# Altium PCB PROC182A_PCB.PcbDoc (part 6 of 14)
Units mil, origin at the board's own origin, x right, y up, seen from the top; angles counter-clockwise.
Board outline 3168.31 x 3700.79 mil, 8 copper layers (Top Layer, L2_GND1, L3_SIG1, L4_PWR1, L5_PWR2, L6_SIG2, L7_GND2, Bottom Layer), stack 58.1 mil thick; 580 components, 391 nets, 8314 pads, 4370 vias.
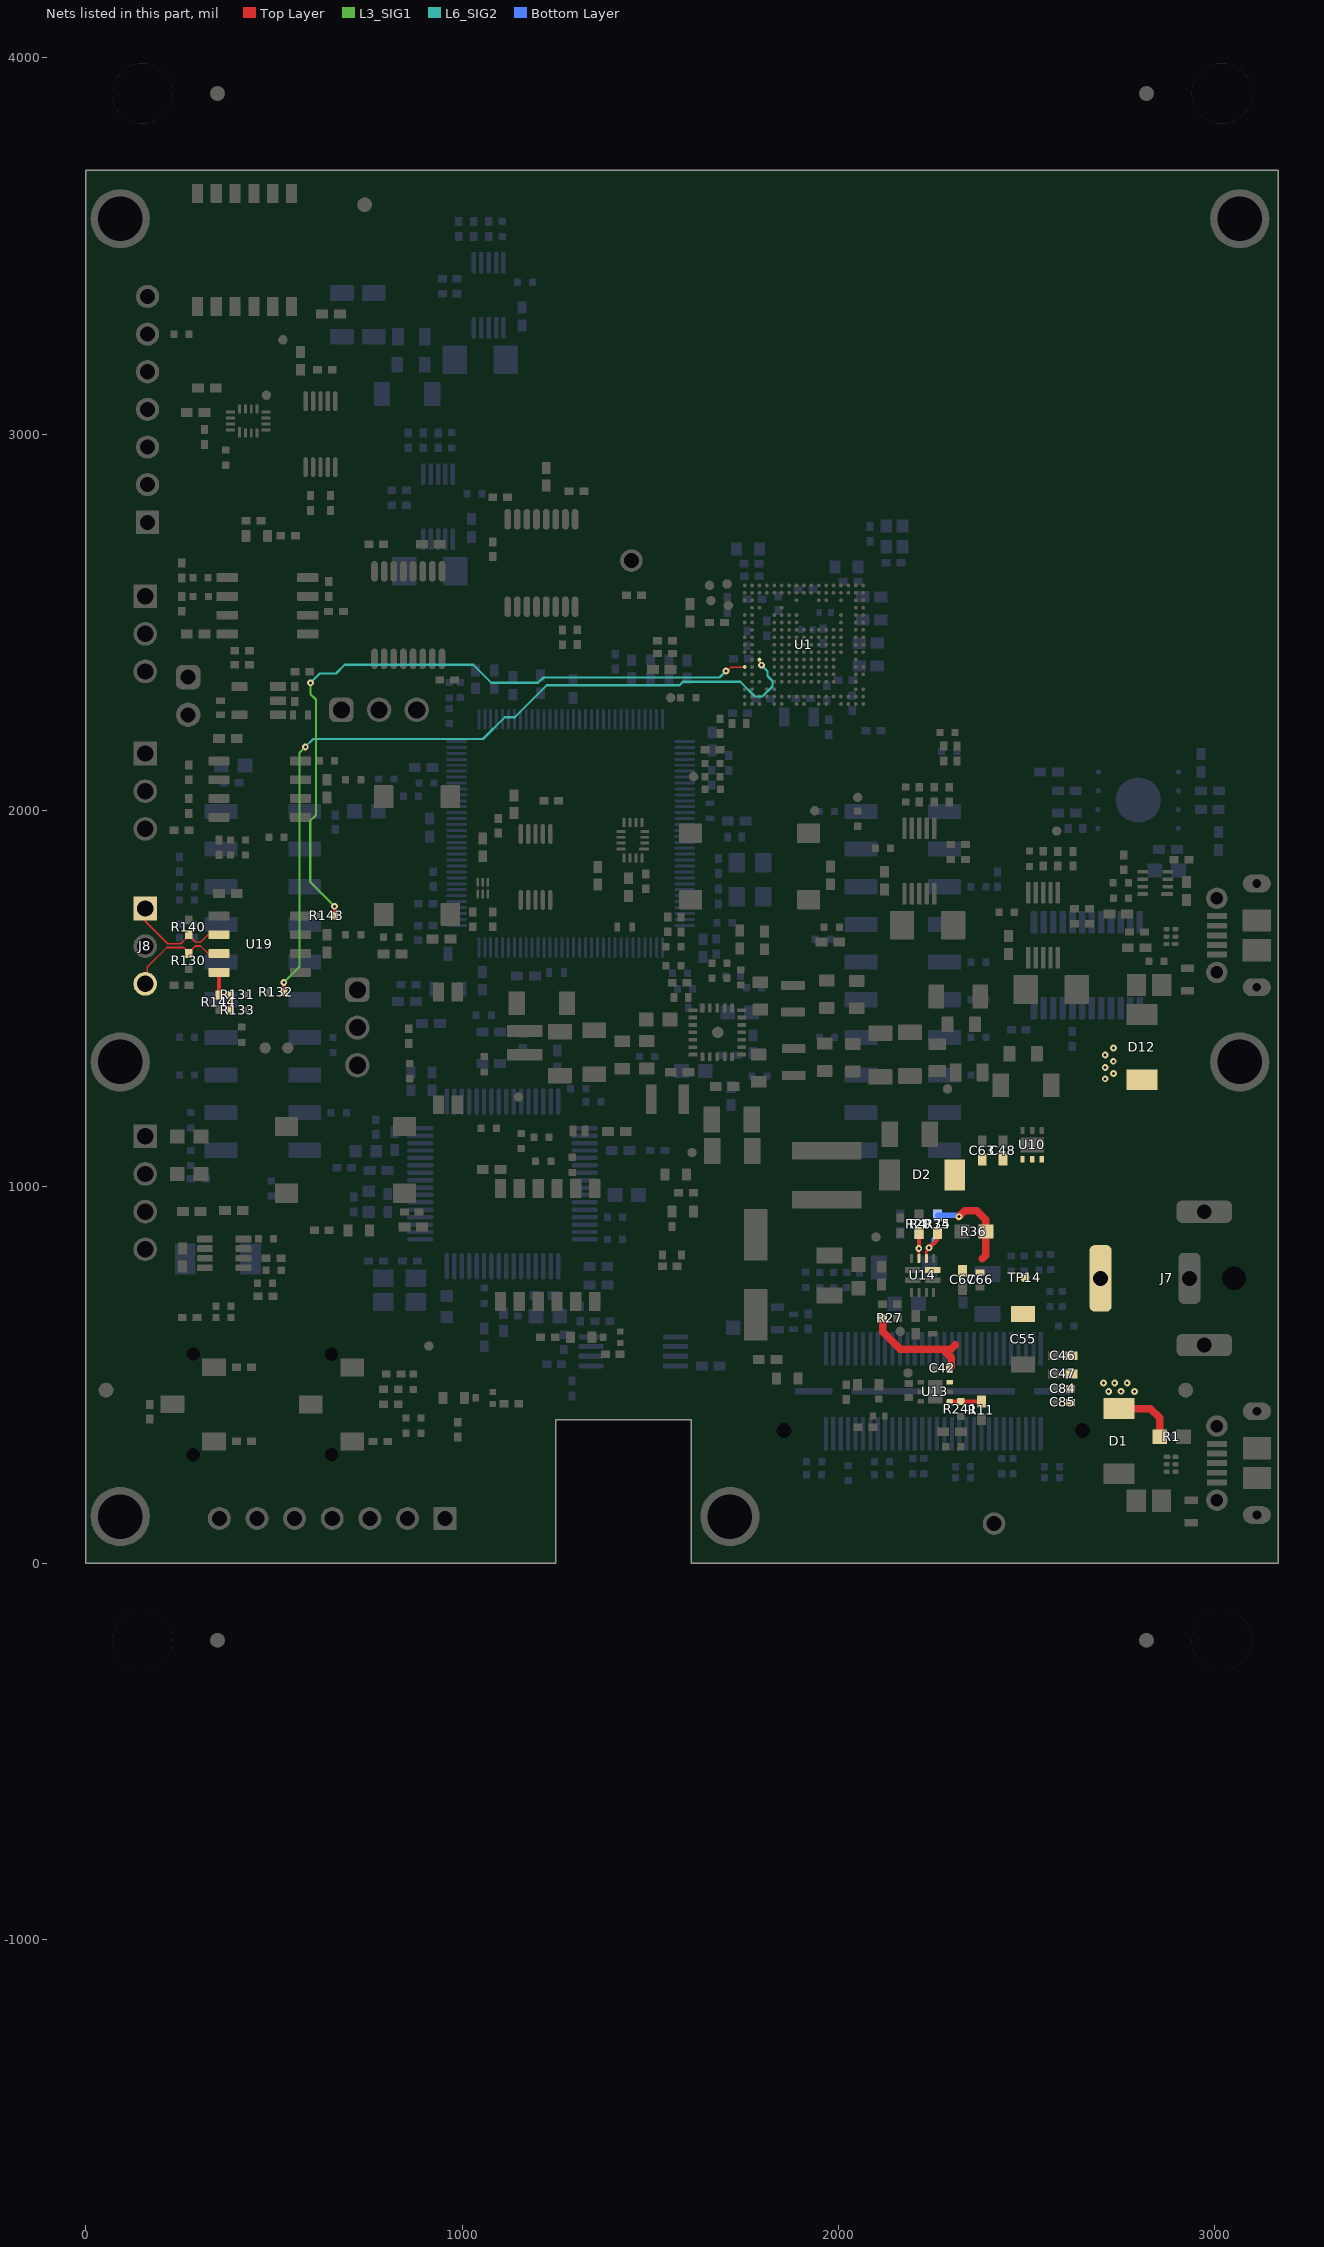
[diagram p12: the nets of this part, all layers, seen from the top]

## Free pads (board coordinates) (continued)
  round 5 on Mech16: 1(836.95,1440.45) 1(836.95,1440.45) 1(836.95,1491.45) 1(836.95,1491.45) 1(848.2,1416.45) 1(848.2,1416.45) 1(848.2,1424.6) 1(848.2,1424.6) 1(848.2,1426.88) 1(848.2,1426.88) 1(848.2,1434.38) 1(848.2,1434.38) 1(848.2,1440.45) 1(848.2,1440.45) 1(857.23,1143.96) 1(857.23,1143.96) 1(857.23,1143.98) 1(857.23,1143.98) 1(857.23,1200.98) 1(857.23,1200.98) 1(857.23,1201) 1(857.23,1201) 1(860.23,1140.98) 1(860.23,1140.98) 1(860.23,1203.98) 1(860.23,1203.98) 1(865.7,1416.45) 1(865.7,1416.45) 1(865.7,1424.6) 1(865.7,1424.6) 1(865.7,1426.88) 1(865.7,1426.88) 1(865.7,1434.38) 1(865.7,1434.38) 1(865.7,1440.45) 1(865.7,1440.45) 1(869.85,1116.48) 1(869.85,1116.48) 1(869.85,1125.03) 1(869.85,1125.03) 1(869.85,1128.67) 1(869.85,1128.67) 1(869.85,1129.93) 1(869.85,1129.93) 1(869.85,1139.9) 1(869.85,1139.9) 1(869.85,1140.98) 1(869.85,1140.98) 1(869.85,1203.98) 1(869.85,1203.98) 1(869.85,1205.07) 1(869.85,1205.07) 1(869.85,1215.03) 1(869.85,1215.03) 1(869.85,1216.29) 1(869.85,1216.29) 1(869.85,1219.93) 1(869.85,1219.93) 1(869.85,1228.48) 1(869.85,1228.48) 1(884.61,1116.48) 1(884.61,1116.48) 1(884.61,1125.03) 1(884.61,1125.03) 1(884.61,1128.67) 1(884.61,1128.67) 1(884.61,1129.93) 1(884.61,1129.93) 1(884.61,1139.9) 1(884.61,1139.9) 1(884.61,1140.98) 1(884.61,1140.98) 1(884.61,1203.98) 1(884.61,1203.98) 1(884.61,1205.07) 1(884.61,1205.07) 1(884.61,1215.03) 1(884.61,1215.03) 1(884.61,1216.29) 1(884.61,1216.29) 1(884.61,1219.93) 1(884.61,1219.93) 1(884.61,1228.48) 1(884.61,1228.48) 1(885.7,1491.45) 1(885.7,1491.45) 1(885.7,1497.51) 1(885.7,1497.51) 1(885.7,1505.01) 1(885.7,1505.01) 1(885.7,1507.3) 1(885.7,1507.3) 1(885.7,1515.45) 1(885.7,1515.45) 1(903.2,1491.45) 1(903.2,1491.45) 1(903.2,1497.51) 1(903.2,1497.51) 1(903.2,1505.01) 1(903.2,1505.01) 1(903.2,1507.3) 1(903.2,1507.3) 1(903.2,1515.45) 1(903.2,1515.45) 1(907.35,1116.48) 1(907.35,1116.48) 1(907.35,1125.03) 1(907.35,1125.03) 1(907.35,1128.67) 1(907.35,1128.67) 1(907.35,1129.93) 1(907.35,1129.93) 1(907.35,1139.9) 1(907.35,1139.9) 1(907.35,1140.98) 1(907.35,1140.98) 1(907.35,1203.98) 1(907.35,1203.98) 1(907.35,1205.07) 1(907.35,1205.07) 1(907.35,1215.03) 1(907.35,1215.03) 1(907.35,1216.29) 1(907.35,1216.29) 1(907.35,1219.93) 1(907.35,1219.93) 1(907.35,1228.48) 1(907.35,1228.48) 1(922.11,1116.48) 1(922.11,1116.48) 1(922.11,1125.03) 1(922.11,1125.03) 1(922.11,1128.67) 1(922.11,1128.67) 1(922.11,1129.93) 1(922.11,1129.93) 1(922.11,1139.9) 1(922.11,1139.9) 1(922.11,1140.98) 1(922.11,1140.98) 1(922.11,1203.98) 1(922.11,1203.98) 1(922.11,1205.07) 1(922.11,1205.07) 1(922.11,1215.03) 1(922.11,1215.03) 1(922.11,1216.29) 1(922.11,1216.29) 1(922.11,1219.93) 1(922.11,1219.93) 1(922.11,1228.48) 1(922.11,1228.48) 1(923.2,1416.45) 1(923.2,1416.45) 1(923.2,1424.6) 1(923.2,1424.6) 1(923.2,1426.88) 1(923.2,1426.88) 1(923.2,1434.38) 1(923.2,1434.38) 1(923.2,1440.45) 1(923.2,1440.45) 1(940.7,1416.45) 1(940.7,1416.45) 1(940.7,1424.6) 1(940.7,1424.6) 1(940.7,1426.88) 1(940.7,1426.88) 1(940.7,1434.38) 1(940.7,1434.38) 1(940.7,1440.45) 1(940.7,1440.45) 1(944.85,1116.48) 1(944.85,1116.48) 1(944.85,1125.03) 1(944.85,1125.03) 1(944.85,1128.67) 1(944.85,1128.67) 1(944.85,1129.93) 1(944.85,1129.93) 1(944.85,1139.9) 1(944.85,1139.9) 1(944.85,1140.98) 1(944.85,1140.98) 1(944.85,1203.98) 1(944.85,1203.98) 1(944.85,1205.07) 1(944.85,1205.07) 1(944.85,1215.03) 1(944.85,1215.03) 1(944.85,1216.29) 1(944.85,1216.29) 1(944.85,1219.93) 1(944.85,1219.93) 1(944.85,1228.48) 1(944.85,1228.48) 1(950.98,1149.81) 1(950.98,1149.81) 1(950.98,1159.8) 1(950.98,1159.8) 1(951.95,1440.45) 1(951.95,1440.45) 1(951.95,1491.45) 1(951.95,1491.45) 1(959.61,1116.48) 1(959.61,1116.48) 1(959.61,1125.03) 1(959.61,1125.03) 1(959.61,1128.67) 1(959.61,1128.67) 1(959.61,1129.93) 1(959.61,1129.93) 1(959.61,1139.9) 1(959.61,1139.9) 1(959.61,1140.98) 1(959.61,1140.98) 1(959.61,1203.98) 1(959.61,1203.98) 1(959.61,1205.07) 1(959.61,1205.07) 1(959.61,1215.03) 1(959.61,1215.03) 1(959.61,1216.29) 1(959.61,1216.29) 1(959.61,1219.93) 1(959.61,1219.93) 1(959.61,1228.48) 1(959.61,1228.48) 1(969.24,1140.98) 1(969.24,1140.98) 1(969.24,1203.98) 1(969.24,1203.98) 1(972.23,1143.96) 1(972.23,1143.96) 1(972.23,1143.98) 1(972.23,1143.98) 1(972.23,1200.98) 1(972.23,1200.98) 1(972.23,1201) 1(972.23,1201) 1(1078.31,-1645.55) 1(1078.31,-1645.55) 1(1078.31,-1145.55) 1(1078.31,-1145.55) 1(1668.61,1080.75) 1(1668.61,1080.75) 1(1668.61,1090.6) 1(1668.61,1090.6) 1(1668.61,1106.35) 1(1668.61,1106.35) 1(1668.61,1116.19) 1(1668.61,1116.19) 1(1668.61,1131.94) 1(1668.61,1131.94) 1(1668.61,1141.78) 1(1668.61,1141.78) 1(1668.61,1157.53) 1(1668.61,1157.53) 1(1668.61,1167.37) 1(1668.61,1167.37) 1(1680.42,1080.75) 1(1680.42,1080.75) 1(1680.42,1090.6) 1(1680.42,1090.6) 1(1680.42,1106.35) 1(1680.42,1106.35) 1(1680.42,1116.19) 1(1680.42,1116.19) 1(1680.42,1131.94) 1(1680.42,1131.94) 1(1680.42,1141.78) 1(1680.42,1141.78) 1(1680.42,1157.53) 1(1680.42,1157.53) 1(1680.42,1167.37) 1(1680.42,1167.37) 1(1685.84,1080.75) 1(1685.84,1080.75) 1(1685.84,1090.6) 1(1685.84,1090.6) 1(1685.84,1106.35) 1(1685.84,1106.35) 1(1685.84,1116.19) 1(1685.84,1116.19) 1(1685.84,1131.94) 1(1685.84,1131.94) 1(1685.84,1141.78) 1(1685.84,1141.78) 1(1685.84,1157.53) 1(1685.84,1157.53) 1(1685.84,1167.37) 1(1685.84,1167.37) 1(1691.06,1080.75) 1(1691.06,1080.75) 1(1691.06,1090.6) 1(1691.06,1090.6) 1(1691.06,1106.35) 1(1691.06,1106.35) 1(1691.06,1116.19) 1(1691.06,1116.19) 1(1691.06,1131.94) 1(1691.06,1131.94) 1(1691.06,1141.78) 1(1691.06,1141.78) 1(1691.06,1157.53) 1(1691.06,1157.53) 1(1691.06,1167.37) 1(1691.06,1167.37) 1(1700.1,1080.75) 1(1700.1,1080.75) 1(1700.1,1090.6) 1(1700.1,1090.6) 1(1700.1,1106.35) 1(1700.1,1106.35) 1(1700.1,1116.19) 1(1700.1,1116.19) 1(1700.1,1131.94) 1(1700.1,1131.94) 1(1700.1,1141.78) 1(1700.1,1141.78) 1(1700.1,1157.53) 1(1700.1,1157.53) 1(1700.1,1167.37) 1(1700.1,1167.37) 1(1706.01,1062.84) 1(1706.01,1062.84) 1(1706.01,1062.84) 1(1706.01,1080.75) 1(1706.01,1080.75) 1(1706.01,1090.6) 1(1706.01,1090.6) 1(1706.01,1106.35) 1(1706.01,1106.35) 1(1706.01,1116.19) 1(1706.01,1116.19) 1(1706.01,1131.94) 1(1706.01,1131.94) 1(1706.01,1141.78) 1(1706.01,1141.78) 1(1706.01,1157.53) 1(1706.01,1157.53) 1(1706.01,1167.37) 1(1706.01,1167.37) 1(1706.01,1184.89) 1(1706.01,1184.89) 1(1706.01,1184.89) 1(1709.77,1066.61) 1(1709.77,1066.61) 1(1709.77,1066.61) 1(1709.77,1181.12) 1(1709.77,1181.12) 1(1709.77,1181.12) 1(1724.56,931.83) 1(1724.56,931.83) 1(1724.56,942.51) 1(1724.56,942.51) 1(1724.56,951.51) 1(1724.56,951.51) 1(1724.56,962.19) 1(1724.56,962.19) 1(1724.56,990.87) 1(1724.56,990.87) 1(1724.56,1001.55) 1(1724.56,1001.55) 1(1724.56,922.83) 1(1724.56,922.83) 1(1724.56,971.19) 1(1724.56,971.19) 1(1724.56,981.87) 1(1724.56,981.87) 1(1724.56,1010.55) 1(1724.56,1010.55) 1(1725.69,1074.65) 1(1725.69,1074.65) 1(1725.69,1090.4) 1(1725.69,1090.4) 1(1734,922.83) 1(1734,922.83) 1(1734,931.83) 1(1734,931.83) 1(1734,942.51) 1(1734,942.51) 1(1734,951.51) 1(1734,951.51) 1(1734,962.19) 1(1734,962.19) 1(1734,971.19) 1(1734,971.19) 1(1734,981.87) 1(1734,981.87) 1(1734,990.87) 1(1734,990.87) 1(1734,1001.55) 1(1734,1001.55) 1(1734,1010.55) 1(1734,1010.55) 1(1738.72,922.83) 1(1738.72,922.83) 1(1738.72,931.83) 1(1738.72,931.83) 1(1738.72,942.51) 1(1738.72,942.51) 1(1738.72,951.51) 1(1738.72,951.51) 1(1738.72,962.19) 1(1738.72,962.19) 1(1738.72,971.19) 1(1738.72,971.19) 1(1738.72,981.87) 1(1738.72,981.87) 1(1738.72,990.87) 1(1738.72,990.87) 1(1738.72,1001.55) 1(1738.72,1001.55) 1(1738.72,1010.55) 1(1738.72,1010.55) 1(1738.85,922.83) 1(1738.85,922.83) 1(1738.85,931.83) 1(1738.85,931.83) 1(1738.85,942.51) 1(1738.85,942.51) 1(1738.85,951.51) 1(1738.85,951.51) 1(1738.85,962.19) 1(1738.85,962.19) 1(1738.85,971.19) 1(1738.85,971.19) 1(1738.85,981.87) 1(1738.85,981.87) 1(1738.85,990.87) 1(1738.85,990.87) 1(1738.85,1001.55) 1(1738.85,1001.55) 1(1738.85,1010.55) 1(1738.85,1010.55) 1(1750.8,922.83) 1(1750.8,922.83) 1(1750.8,931.83) 1(1750.8,931.83) 1(1750.8,942.51) 1(1750.8,942.51) 1(1750.8,951.51) 1(1750.8,951.51) 1(1750.8,962.19) 1(1750.8,962.19) 1(1750.8,971.19) 1(1750.8,971.19) 1(1750.8,981.87) 1(1750.8,981.87) 1(1750.8,990.87) 1(1750.8,990.87) 1(1750.8,1001.55) 1(1750.8,1001.55) 1(1750.8,1010.55) 1(1750.8,1010.55) 1(1762.06,912.69) 1(1762.06,912.69) 1(1762.06,922.83) 1(1762.06,922.83) 1(1762.06,931.83) 1(1762.06,931.83) 1(1762.06,942.51) 1(1762.06,942.51) 1(1762.06,951.51) 1(1762.06,951.51) 1(1762.06,962.19) 1(1762.06,962.19) 1(1762.06,971.19) 1(1762.06,971.19) 1(1762.06,981.87) 1(1762.06,981.87) 1(1762.06,990.87) 1(1762.06,990.87) 1(1762.06,1001.55) 1(1762.06,1001.55) 1(1762.06,1010.55) 1(1762.06,1010.55) 1(1762.06,1020.69) 1(1762.06,1020.69) 1(1762.07,912.59) 1(1762.07,912.59) 1(1762.07,1020.8) 1(1762.07,1020.8) 1(1763.15,145.77) 1(1763.15,145.77) 1(1763.15,225.77) 1(1763.15,225.77) 1(1763.15,541.91) 1(1763.15,541.91) 1(1763.15,621.91) 1(1763.15,621.91) 1(1766.96,907.7) 1(1766.96,907.7) 1(1766.96,1025.69) 1(1766.96,1025.69) 1(1767.06,907.69) 1(1767.06,907.69) 1(1767.06,1025.69) 1(1767.06,1025.69) 1(1769.06,928.69) 1(1769.06,928.69) 1(1782.87,-204.39) 1(1782.87,-204.39) 1(1782.87,-193.71) 1(1782.87,-193.71) 1(1782.87,-184.71) 1(1782.87,-184.71) 1(1782.87,-174.03) 1(1782.87,-174.03) 1(1782.87,-145.35) 1(1782.87,-145.35) 1(1782.87,-134.67) 1(1782.87,-134.67) 1(1782.87,-213.39) 1(1782.87,-213.39) 1(1782.87,-165.03) 1(1782.87,-165.03) 1(1782.87,-154.35) 1(1782.87,-154.35) 1(1782.87,-125.67) 1(1782.87,-125.67) 1(1792.31,-213.39) 1(1792.31,-213.39) 1(1792.31,-204.39) 1(1792.31,-204.39) 1(1792.31,-193.71) 1(1792.31,-193.71) 1(1792.31,-184.71) 1(1792.31,-184.71) 1(1792.31,-174.03) 1(1792.31,-174.03) 1(1792.31,-165.03) 1(1792.31,-165.03) 1(1792.31,-154.35) 1(1792.31,-154.35) 1(1792.31,-145.35) 1(1792.31,-145.35) 1(1792.31,-134.67) 1(1792.31,-134.67) 1(1792.31,-125.67) 1(1792.31,-125.67) 1(1797.02,-213.39) 1(1797.02,-213.39) 1(1797.02,-204.39) 1(1797.02,-204.39) 1(1797.02,-193.71) 1(1797.02,-193.71) 1(1797.02,-184.71) 1(1797.02,-184.71) 1(1797.02,-174.03) 1(1797.02,-174.03) 1(1797.02,-165.03) 1(1797.02,-165.03) 1(1797.02,-154.35) 1(1797.02,-154.35) 1(1797.02,-145.35) 1(1797.02,-145.35) 1(1797.02,-134.67) 1(1797.02,-134.67) 1(1797.02,-125.67) 1(1797.02,-125.67) 1(1797.06,928.69) 1(1797.06,928.69) 1(1797.15,-213.39) 1(1797.15,-213.39) 1(1797.15,-204.39) 1(1797.15,-204.39) 1(1797.15,-193.71) 1(1797.15,-193.71) 1(1797.15,-184.71) 1(1797.15,-184.71) 1(1797.15,-174.03) 1(1797.15,-174.03) 1(1797.15,-165.03) 1(1797.15,-165.03) 1(1797.15,-154.35) 1(1797.15,-154.35) 1(1797.15,-145.35) 1(1797.15,-145.35) 1(1797.15,-134.67) 1(1797.15,-134.67) 1(1797.15,-125.67) 1(1797.15,-125.67) 1(1809.11,-213.39) 1(1809.11,-213.39) 1(1809.11,-204.39) 1(1809.11,-204.39) 1(1809.11,-193.71) 1(1809.11,-193.71) 1(1809.11,-184.71) 1(1809.11,-184.71) 1(1809.11,-174.03) 1(1809.11,-174.03) 1(1809.11,-165.03) 1(1809.11,-165.03) 1(1809.11,-154.35) 1(1809.11,-154.35) 1(1809.11,-145.35) 1(1809.11,-145.35) 1(1809.11,-134.67) 1(1809.11,-134.67) 1(1809.11,-125.67) 1(1809.11,-125.67) 1(1820.37,-223.53) 1(1820.37,-223.53) 1(1820.37,-213.39) 1(1820.37,-213.39) 1(1820.37,-204.39) 1(1820.37,-204.39) 1(1820.37,-193.71) 1(1820.37,-193.71) 1(1820.37,-184.71) 1(1820.37,-184.71) 1(1820.37,-174.03) 1(1820.37,-174.03) 1(1820.37,-165.03) 1(1820.37,-165.03) 1(1820.37,-154.35) 1(1820.37,-154.35) 1(1820.37,-145.35) 1(1820.37,-145.35) 1(1820.37,-134.67) 1(1820.37,-134.67) 1(1820.37,-125.67) 1(1820.37,-125.67) 1(1820.37,-115.53) 1(1820.37,-115.53) 1(1820.37,-223.64) 1(1820.37,-223.64) 1(1820.37,-115.42) 1(1820.37,-115.42) 1(1825.26,-228.53) 1(1825.26,-228.53) 1(1825.26,-110.53) 1(1825.26,-110.53) 1(1825.37,-228.53) 1(1825.37,-228.53) 1(1825.37,-110.53) 1(1825.37,-110.53) 1(1827.37,-207.53) 1(1827.37,-207.53) 1(1855.37,-207.53) 1(1855.37,-207.53) 1(1875.06,907.69) 1(1875.06,907.69) 1(1875.06,1025.69) 1(1875.06,1025.69) 1(1875.17,907.7) 1(1875.17,907.7) 1(1875.17,1025.69) 1(1875.17,1025.69) 1(1879.41,1066.61) 1(1879.41,1066.61) 1(1879.41,1066.61) 1(1879.41,1181.12) 1(1879.41,1181.12) 1(1879.41,1181.12) 1(1880.06,912.59) 1(1880.06,912.59) 1(1880.06,1020.8) 1(1880.06,1020.8) 1(1880.06,912.69) 1(1880.06,912.69) 1(1880.06,922.83) 1(1880.06,922.83) 1(1880.06,931.83) 1(1880.06,931.83) 1(1880.06,942.51) 1(1880.06,942.51) 1(1880.06,951.51) 1(1880.06,951.51) 1(1880.06,962.19) 1(1880.06,962.19) 1(1880.06,971.19) 1(1880.06,971.19) 1(1880.06,981.87) 1(1880.06,981.87) 1(1880.06,990.87) 1(1880.06,990.87) 1(1880.06,1001.55) 1(1880.06,1001.55) 1(1880.06,1010.55) 1(1880.06,1010.55) 1(1880.06,1020.69) 1(1880.06,1020.69) 1(1883.17,1062.84) 1(1883.17,1062.84) 1(1883.17,1062.84) 1(1883.17,1080.75) 1(1883.17,1080.75) 1(1883.17,1090.6) 1(1883.17,1090.6) 1(1883.17,1106.35) 1(1883.17,1106.35) 1(1883.17,1116.19) 1(1883.17,1116.19) 1(1883.17,1131.94) 1(1883.17,1131.94) 1(1883.17,1141.78) 1(1883.17,1141.78) 1(1883.17,1157.53) 1(1883.17,1157.53) 1(1883.17,1167.37) 1(1883.17,1167.37) 1(1883.17,1184.89) 1(1883.17,1184.89) 1(1883.17,1184.89) 1(1889.08,1080.75) 1(1889.08,1080.75) 1(1889.08,1090.6) 1(1889.08,1090.6) 1(1889.08,1106.35) 1(1889.08,1106.35) 1(1889.08,1116.19) 1(1889.08,1116.19) 1(1889.08,1131.94) 1(1889.08,1131.94) 1(1889.08,1141.78) 1(1889.08,1141.78) 1(1889.08,1157.53) 1(1889.08,1157.53) 1(1889.08,1167.37) 1(1889.08,1167.37) 1(1891.33,922.83) 1(1891.33,922.83) 1(1891.33,931.83) 1(1891.33,931.83) 1(1891.33,942.51) 1(1891.33,942.51) 1(1891.33,951.51) 1(1891.33,951.51) 1(1891.33,962.19) 1(1891.33,962.19) 1(1891.33,971.19) 1(1891.33,971.19) 1(1891.33,981.87) 1(1891.33,981.87) 1(1891.33,1010.55) 1(1891.33,1010.55) 1(1891.33,990.87) 1(1891.33,990.87) 1(1891.33,1001.55) 1(1891.33,1001.55) 1(1898.12,1080.75) 1(1898.12,1080.75) 1(1898.12,1090.6) 1(1898.12,1090.6) 1(1898.12,1106.35) 1(1898.12,1106.35) 1(1898.12,1116.19) 1(1898.12,1116.19) 1(1898.12,1131.94) 1(1898.12,1131.94) 1(1898.12,1141.78) 1(1898.12,1141.78) 1(1898.12,1157.53) 1(1898.12,1157.53) 1(1898.12,1167.37) 1(1898.12,1167.37) 1(1903.28,922.83) 1(1903.28,922.83) 1(1903.28,931.83) 1(1903.28,931.83) 1(1903.28,942.51) 1(1903.28,942.51) 1(1903.28,951.51) 1(1903.28,951.51) 1(1903.28,962.19) 1(1903.28,962.19) 1(1903.28,971.19) 1(1903.28,971.19) 1(1903.28,981.87) 1(1903.28,981.87) 1(1903.28,990.87) 1(1903.28,990.87) 1(1903.28,1001.55) 1(1903.28,1001.55) 1(1903.28,1010.55) 1(1903.28,1010.55) 1(1903.34,1080.75) 1(1903.34,1080.75) 1(1903.34,1090.6) 1(1903.34,1090.6) 1(1903.34,1106.35) 1(1903.34,1106.35) 1(1903.34,1116.19) 1(1903.34,1116.19) 1(1903.34,1131.94) 1(1903.34,1131.94) 1(1903.34,1141.78) 1(1903.34,1141.78) 1(1903.34,1157.53) 1(1903.34,1157.53) 1(1903.34,1167.37) 1(1903.34,1167.37) 1(1903.41,990.87) 1(1903.41,990.87) 1(1903.41,1001.55) 1(1903.41,1001.55) 1(1903.41,922.83) 1(1903.41,922.83) 1(1903.41,931.83) 1(1903.41,931.83) 1(1903.41,942.51) 1(1903.41,942.51) 1(1903.41,951.51) 1(1903.41,951.51) 1(1903.41,962.19) 1(1903.41,962.19) 1(1903.41,971.19) 1(1903.41,971.19) 1(1903.41,981.87) 1(1903.41,981.87) 1(1903.41,1010.55) 1(1903.41,1010.55) 1(1908.13,922.83) 1(1908.13,922.83) 1(1908.13,931.83) 1(1908.13,931.83) 1(1908.13,942.51) 1(1908.13,942.51) 1(1908.13,951.51) 1(1908.13,951.51) 1(1908.13,962.19) 1(1908.13,962.19) 1(1908.13,971.19) 1(1908.13,971.19) 1(1908.13,981.87) 1(1908.13,981.87) 1(1908.13,990.87) 1(1908.13,990.87) 1(1908.13,1001.55) 1(1908.13,1001.55) 1(1908.13,1010.55) 1(1908.13,1010.55) 1(1908.76,1080.75) 1(1908.76,1080.75) 1(1908.76,1090.6) 1(1908.76,1090.6) 1(1908.76,1106.35) 1(1908.76,1106.35) 1(1908.76,1116.19) 1(1908.76,1116.19) 1(1908.76,1131.94) 1(1908.76,1131.94) 1(1908.76,1141.78) 1(1908.76,1141.78) 1(1908.76,1157.53) 1(1908.76,1157.53) 1(1908.76,1167.37) 1(1908.76,1167.37) 1(1909.15,541.91) 1(1909.15,541.91) 1(1909.15,621.91) 1(1909.15,621.91) 1(1911.15,145.77) 1(1911.15,145.77) 1(1911.15,145.91) 1(1911.15,145.91) 1(1911.15,225.77) 1(1911.15,225.77) 1(1911.15,225.91) 1(1911.15,225.91) 1(1911.15,541.91) 1(1911.15,541.91) 1(1911.15,621.91) 1(1911.15,621.91) 1(1917.56,922.83) 1(1917.56,922.83) 1(1917.56,931.83) 1(1917.56,931.83) 1(1917.56,942.51) 1(1917.56,942.51) 1(1917.56,951.51) 1(1917.56,951.51) 1(1917.56,962.19) 1(1917.56,962.19) 1(1917.56,971.19) 1(1917.56,971.19) 1(1917.56,981.87) 1(1917.56,981.87) 1(1917.56,990.87) 1(1917.56,990.87) 1(1917.56,1001.55) 1(1917.56,1001.55) 1(1917.56,1010.55) 1(1917.56,1010.55) 1(1920.58,1080.75) 1(1920.58,1080.75) 1(1920.58,1090.6) 1(1920.58,1090.6) 1(1920.58,1106.35) 1(1920.58,1106.35) 1(1920.58,1116.19) 1(1920.58,1116.19) 1(1920.58,1131.94) 1(1920.58,1131.94) 1(1920.58,1141.78) 1(1920.58,1141.78) 1(1920.58,1157.53) 1(1920.58,1157.53) 1(1920.58,1167.37) 1(1920.58,1167.37) 1(1933.37,-228.53) 1(1933.37,-228.53) 1(1933.37,-110.53) 1(1933.37,-110.53) 1(1933.48,-228.53) 1(1933.48,-228.53) 1(1933.48,-110.53) 1(1933.48,-110.53) 1(1938.37,-223.64) 1(1938.37,-223.64) 1(1938.37,-115.42) 1(1938.37,-115.42) 1(1938.37,-223.53) 1(1938.37,-223.53) 1(1938.37,-213.39) 1(1938.37,-213.39) 1(1938.37,-204.39) 1(1938.37,-204.39) 1(1938.37,-193.71) 1(1938.37,-193.71) 1(1938.37,-184.71) 1(1938.37,-184.71) 1(1938.37,-174.03) 1(1938.37,-174.03) 1(1938.37,-165.03) 1(1938.37,-165.03) 1(1938.37,-154.35) 1(1938.37,-154.35) 1(1938.37,-145.35) 1(1938.37,-145.35) 1(1938.37,-134.67) 1(1938.37,-134.67) 1(1938.37,-125.67) 1(1938.37,-125.67) 1(1938.37,-115.53) 1(1938.37,-115.53) 1(1949.63,-213.39) 1(1949.63,-213.39) 1(1949.63,-204.39) 1(1949.63,-204.39) 1(1949.63,-193.71) 1(1949.63,-193.71) 1(1949.63,-184.71) 1(1949.63,-184.71) 1(1949.63,-174.03) 1(1949.63,-174.03) 1(1949.63,-165.03) 1(1949.63,-165.03) 1(1949.63,-154.35) 1(1949.63,-154.35) 1(1949.63,-125.67) 1(1949.63,-125.67) 1(1949.63,-145.35) 1(1949.63,-145.35) 1(1949.63,-134.67) 1(1949.63,-134.67) 1(1961.59,-213.39) 1(1961.59,-213.39) 1(1961.59,-204.39) 1(1961.59,-204.39) 1(1961.59,-193.71) 1(1961.59,-193.71) 1(1961.59,-184.71) 1(1961.59,-184.71) 1(1961.59,-174.03) 1(1961.59,-174.03) 1(1961.59,-165.03) 1(1961.59,-165.03) 1(1961.59,-154.35) 1(1961.59,-154.35) 1(1961.59,-145.35) 1(1961.59,-145.35) 1(1961.59,-134.67) 1(1961.59,-134.67) 1(1961.59,-125.67) 1(1961.59,-125.67) 1(1961.72,-145.35) 1(1961.72,-145.35) 1(1961.72,-134.67) 1(1961.72,-134.67) 1(1961.72,-213.39) 1(1961.72,-213.39) 1(1961.72,-204.39) 1(1961.72,-204.39) 1(1961.72,-193.71) 1(1961.72,-193.71) 1(1961.72,-184.71) 1(1961.72,-184.71) 1(1961.72,-174.03) 1(1961.72,-174.03) 1(1961.72,-165.03) 1(1961.72,-165.03) 1(1961.72,-154.35) 1(1961.72,-154.35) 1(1961.72,-125.67) 1(1961.72,-125.67) 1(1966.44,-213.39) 1(1966.44,-213.39) 1(1966.44,-204.39) 1(1966.44,-204.39) 1(1966.44,-193.71) 1(1966.44,-193.71) 1(1966.44,-184.71) 1(1966.44,-184.71) 1(1966.44,-174.03) 1(1966.44,-174.03) 1(1966.44,-165.03) 1(1966.44,-165.03) 1(1966.44,-154.35) 1(1966.44,-154.35) 1(1966.44,-145.35) 1(1966.44,-145.35) 1(1966.44,-134.67) 1(1966.44,-134.67) 1(1966.44,-125.67) 1(1966.44,-125.67) 1(1975.87,-213.39) 1(1975.87,-213.39) 1(1975.87,-204.39) 1(1975.87,-204.39) 1(1975.87,-193.71) 1(1975.87,-193.71) 1(1975.87,-184.71) 1(1975.87,-184.71) 1(1975.87,-174.03) 1(1975.87,-174.03) 1(1975.87,-165.03) 1(1975.87,-165.03) 1(1975.87,-154.35) 1(1975.87,-154.35) 1(1975.87,-145.35) 1(1975.87,-145.35) 1(1975.87,-134.67) 1(1975.87,-134.67) 1(1975.87,-125.67) 1(1975.87,-125.67) 1(1978.31,-1645.55) 1(1978.31,-1645.55) 1(1978.31,-1145.55) 1(1978.31,-1145.55) 1(2057.15,541.91) 1(2057.15,541.91) 1(2057.15,621.91) 1(2057.15,621.91) 1(2059.15,145.91) 1(2059.15,145.91) 1(2059.15,225.91) 1(2059.15,225.91) 1(2092.93,-1615.05) 1(2092.93,-1615.05) 1(2092.93,-1606.06) 1(2092.93,-1606.06) 1(2092.93,-1467.05) 1(2092.93,-1467.05) 1(2092.93,-1458.05) 1(2092.93,-1458.05) 1(2242.75,2.09) 1(2242.75,2.09) 1(2242.75,11.09) 1(2242.75,11.09) 1(2242.75,21.77) 1(2242.75,21.77) 1(2242.75,30.77) 1(2242.75,30.77) 1(2242.75,41.45) 1(2242.75,41.45) 1(2242.75,50.45) 1(2242.75,50.45) 1(2242.75,61.13) 1(2242.75,61.13) 1(2242.75,70.13) 1(2242.75,70.13) 1(2242.75,80.81) 1(2242.75,80.81) 1(2242.75,89.81) 1(2242.75,89.81) 1(2252.19,2.09) 1(2252.19,2.09) 1(2252.19,11.09) 1(2252.19,11.09) 1(2252.19,21.77) 1(2252.19,21.77) 1(2252.19,30.77) 1(2252.19,30.77) 1(2252.19,41.45) 1(2252.19,41.45) 1(2252.19,50.45) 1(2252.19,50.45) 1(2252.19,61.13) 1(2252.19,61.13) 1(2252.19,70.13) 1(2252.19,70.13) 1(2252.19,80.81) 1(2252.19,80.81) 1(2252.19,89.81) 1(2252.19,89.81) 1(2256.91,2.09) 1(2256.91,2.09) 1(2256.91,11.09) 1(2256.91,11.09) 1(2256.91,21.77) 1(2256.91,21.77) 1(2256.91,30.77) 1(2256.91,30.77) 1(2256.91,41.45) 1(2256.91,41.45) 1(2256.91,50.45) 1(2256.91,50.45) 1(2256.91,61.13) 1(2256.91,61.13) 1(2256.91,70.13) 1(2256.91,70.13) 1(2256.91,80.81) 1(2256.91,80.81) 1(2256.91,89.81) 1(2256.91,89.81) 1(2257.04,2.09) 1(2257.04,2.09) 1(2257.04,11.09) 1(2257.04,11.09) 1(2257.04,21.77) 1(2257.04,21.77) 1(2257.04,30.77) 1(2257.04,30.77) 1(2257.04,41.45) 1(2257.04,41.45) 1(2257.04,50.45) 1(2257.04,50.45) 1(2257.04,61.13) 1(2257.04,61.13) 1(2257.04,70.13) 1(2257.04,70.13) 1(2257.04,80.81) 1(2257.04,80.81) 1(2257.04,89.81) 1(2257.04,89.81) 1(2268.99,2.09) 1(2268.99,2.09) 1(2268.99,11.09) 1(2268.99,11.09) 1(2268.99,21.77) 1(2268.99,21.77) 1(2268.99,30.77) 1(2268.99,30.77) 1(2268.99,41.45) 1(2268.99,41.45) 1(2268.99,50.45) 1(2268.99,50.45) 1(2268.99,61.13) 1(2268.99,61.13) 1(2268.99,70.13) 1(2268.99,70.13) 1(2268.99,80.81) 1(2268.99,80.81) 1(2268.99,89.81) 1(2268.99,89.81) 1(2280.25,-8.05) 1(2280.25,-8.05) 1(2280.25,2.09) 1(2280.25,2.09) 1(2280.25,11.09) 1(2280.25,11.09) 1(2280.25,21.77) 1(2280.25,21.77) 1(2280.25,30.77) 1(2280.25,30.77) 1(2280.25,41.45) 1(2280.25,41.45) 1(2280.25,50.45) 1(2280.25,50.45) 1(2280.25,61.13) 1(2280.25,61.13) 1(2280.25,70.13) 1(2280.25,70.13) 1(2280.25,80.81) 1(2280.25,80.81) 1(2280.25,89.81) 1(2280.25,89.81) 1(2280.25,99.95) 1(2280.25,99.95) 1(2280.25,-8.16) 1(2280.25,-8.16) 1(2280.25,100.06) 1(2280.25,100.06) 1(2281.3,-1390.5) 1(2281.3,-1390.5) 1(2281.3,-1242.5) 1(2281.3,-1242.5) 1(2285.15,-13.05) 1(2285.15,-13.05) 1(2285.15,104.95) 1(2285.15,104.95) 1(2285.25,-13.05) 1(2285.25,-13.05) 1(2285.25,104.95) 1(2285.25,104.95) 1(2359.93,-1615.05) 1(2359.93,-1458.05) 1(2361.3,-1390.5) 1(2361.3,-1390.5) 1(2361.3,-1242.5) 1(2361.3,-1242.5) 1(2363.25,83.95) 1(2363.25,83.95) 1(2371.3,-1390.5) 1(2371.3,-1390.5) 1(2371.3,-1242.5) 1(2371.3,-1242.5) 1(2391.25,83.95) 1(2391.25,83.95) 1(2393.25,-13.05) 1(2393.25,-13.05) 1(2393.25,104.95) 1(2393.25,104.95) 1(2393.36,-13.05) 1(2393.36,-13.05) 1(2393.36,104.95) 1(2393.36,104.95) 1(2398.25,-8.16) 1(2398.25,-8.16) 1(2398.25,100.06) 1(2398.25,100.06) 1(2398.25,-8.05) 1(2398.25,-8.05) 1(2398.25,2.09) 1(2398.25,2.09) 1(2398.25,11.09) 1(2398.25,11.09) 1(2398.25,21.77) 1(2398.25,21.77) 1(2398.25,30.77) 1(2398.25,30.77) 1(2398.25,41.45) 1(2398.25,41.45) 1(2398.25,50.45) 1(2398.25,50.45) 1(2398.25,61.13) 1(2398.25,61.13) 1(2398.25,70.13) 1(2398.25,70.13) 1(2398.25,80.81) 1(2398.25,80.81) 1(2398.25,89.81) 1(2398.25,89.81) 1(2398.25,99.95) 1(2398.25,99.95) 1(2409.52,2.09) 1(2409.52,2.09) 1(2409.52,11.09) 1(2409.52,11.09) 1(2409.52,21.77) 1(2409.52,21.77) 1(2409.52,30.77) 1(2409.52,30.77) 1(2409.52,41.45) 1(2409.52,41.45) 1(2409.52,50.45) 1(2409.52,50.45) 1(2409.52,61.13) 1(2409.52,61.13) 1(2409.52,70.13) 1(2409.52,70.13) 1(2409.52,80.81) 1(2409.52,80.81) 1(2409.52,89.81) 1(2409.52,89.81) 1(2421.47,2.09) 1(2421.47,2.09) 1(2421.47,11.09) 1(2421.47,11.09) 1(2421.47,21.77) 1(2421.47,21.77) 1(2421.47,30.77) 1(2421.47,30.77) 1(2421.47,41.45) 1(2421.47,41.45) 1(2421.47,50.45) 1(2421.47,50.45) 1(2421.47,61.13) 1(2421.47,61.13) 1(2421.47,70.13) 1(2421.47,70.13) 1(2421.47,80.81) 1(2421.47,80.81) 1(2421.47,89.81) 1(2421.47,89.81) 1(2421.6,2.09) 1(2421.6,2.09) 1(2421.6,11.09) 1(2421.6,11.09) 1(2421.6,21.77) 1(2421.6,21.77) 1(2421.6,30.77) 1(2421.6,30.77) 1(2421.6,41.45) 1(2421.6,41.45) 1(2421.6,50.45) 1(2421.6,50.45) 1(2421.6,61.13) 1(2421.6,61.13) 1(2421.6,70.13) 1(2421.6,70.13) 1(2421.6,80.81) 1(2421.6,80.81) 1(2421.6,89.81) 1(2421.6,89.81) 1(2426.32,2.09) 1(2426.32,2.09) 1(2426.32,11.09) 1(2426.32,11.09) 1(2426.32,21.77) 1(2426.32,21.77) 1(2426.32,30.77) 1(2426.32,30.77) 1(2426.32,41.45) 1(2426.32,41.45) 1(2426.32,50.45) 1(2426.32,50.45) 1(2426.32,61.13) 1(2426.32,61.13) 1(2426.32,70.13) 1(2426.32,70.13) 1(2426.32,80.81) 1(2426.32,80.81) 1(2426.32,89.81) 1(2426.32,89.81) 1(2435.75,2.09) 1(2435.75,2.09) 1(2435.75,11.09) 1(2435.75,11.09) 1(2435.75,21.77) 1(2435.75,21.77) 1(2435.75,30.77) 1(2435.75,30.77) 1(2435.75,41.45) 1(2435.75,41.45) 1(2435.75,50.45) 1(2435.75,50.45) 1(2435.75,61.13) 1(2435.75,61.13) 1(2435.75,70.13) 1(2435.75,70.13) 1(2435.75,80.81) 1(2435.75,80.81) 1(2435.75,89.81) 1(2435.75,89.81) 1(2451.3,-1390.5) 1(2451.3,-1390.5) 1(2451.3,-1242.5) 1(2451.3,-1242.5) 1(2521.3,2417.5) 1(2521.3,2417.5) 1(2521.3,2565.5) 1(2521.3,2565.5) 1(2601.3,2417.5) 1(2601.3,2417.5) 1(2601.3,2565.5) 1(2601.3,2565.5) 1(2638.2,1524.19) 1(2638.2,1524.19) 1(2638.2,1543.88) 1(2638.2,1543.88) 1(2638.2,1564.15) 1(2638.2,1564.15) 1(2638.2,1587.18) 1(2638.2,1587.18) 1(2638.2,1681.67) 1(2638.2,1681.67) 1(2638.2,1704.7) 1(2638.2,1704.7) 1(2638.2,1724.98) 1(2638.2,1724.98) 1(2638.2,1744.66) 1(2638.2,1744.66) 1(2638.2,2199.19) 1(2638.2,2199.19) 1(2638.2,2218.88) 1(2638.2,2218.88) 1(2638.2,2239.15) 1(2638.2,2239.15) 1(2638.2,2262.18) 1(2638.2,2262.18) 1(2638.2,2356.67) 1(2638.2,2356.67) 1(2638.2,2379.7) 1(2638.2,2379.7) 1(2638.2,2399.98) 1(2638.2,2399.98) 1(2638.2,2419.66) 1(2638.2,2419.66) 1(2650.02,1486.79) 1(2650.02,1486.79) 1(2650.02,1508.44) 1(2650.02,1508.44) 1(2650.02,1524.19) 1(2650.02,1524.19) 1(2650.02,1744.66) 1(2650.02,1744.66) 1(2650.02,1760.41) 1(2650.02,1760.41) 1(2650.02,1782.06) 1(2650.02,1782.06) 1(2650.02,2161.79) 1(2650.02,2161.79) 1(2650.02,2183.44) 1(2650.02,2183.44) 1(2650.02,2199.19) 1(2650.02,2199.19) 1(2650.02,2419.66) 1(2650.02,2419.66) 1(2650.02,2435.41) 1(2650.02,2435.41) 1(2650.02,2457.06) 1(2650.02,2457.06) 1(2835.06,1486.79) 1(2835.06,1486.79) 1(2835.06,1486.79) 1(2835.06,1498.6) 1(2835.06,1508.44) 1(2835.06,1508.44) 1(2835.06,1508.44) 1(2835.06,1760.41) 1(2835.06,1760.41) 1(2835.06,1760.41) 1(2835.06,1770.25) 1(2835.06,1782.06) 1(2835.06,1782.06) 1(2835.06,1782.06) 1(2835.06,2161.79) 1(2835.06,2161.79) 1(2835.06,2161.79) 1(2835.06,2173.6) 1(2835.06,2183.44) 1(2835.06,2183.44) 1(2835.06,2183.44) 1(2835.06,2435.41) 1(2835.06,2435.41) 1(2835.06,2435.41) 1(2835.06,2445.25) 1(2835.06,2457.06) 1(2835.06,2457.06) 1(2835.06,2457.06) 1(2835.18,1498.6) 1(2835.18,1770.25) 1(2835.18,2173.6) 1(2835.18,2445.25) 1(2835.18,1498.6) 1(2835.18,1770.25) 1(2835.18,2173.6) 1(2835.18,2445.25) 1(2837.84,1508.44) 1(2837.84,1508.44) 1(2837.84,1508.44) 1(2837.84,1760.41) 1(2837.84,1760.41) 1(2837.84,1760.41) 1(2837.84,2183.44) 1(2837.84,2183.44) 1(2837.84,2183.44) 1(2837.84,2435.41) 1(2837.84,2435.41) 1(2837.84,2435.41) 1(2837.99,1480.2) 1(2837.99,1480.2) 1(2837.99,1788.65) 1(2837.99,1788.65) 1(2837.99,2155.2) 1(2837.99,2155.2) 1(2837.99,2463.65) 1(2837.99,2463.65) 1(2838.09,1760.4) 1(2838.09,1760.4) 1(2838.09,2435.4) 1(2838.09,2435.4) 1(2838.19,1508.46) 1(2838.19,1508.46) 1(2838.19,2183.46) 1(2838.19,2183.46) 1(2838.33,1760.37) 1(2838.33,1760.37) 1(2838.33,2435.37) 1(2838.33,2435.37) 1(2838.43,1508.5) 1(2838.43,1508.5) 1(2838.43,2183.5) 1(2838.43,2183.5) 1(2838.58,1760.32) 1(2838.58,1760.32) 1(2838.58,2435.32) 1(2838.58,2435.32) 1(2838.68,1508.56) 1(2838.68,1508.56) 1(2838.68,2183.56) 1(2838.68,2183.56) 1(2838.82,1760.25) 1(2838.82,1760.25) 1(2838.82,2435.25) 1(2838.82,2435.25) 1(2838.92,1508.63) 1(2838.92,1508.63) 1(2838.92,2183.63) 1(2838.92,2183.63) 1(2839.06,1760.17) 1(2839.06,1760.17) 1(2839.06,2435.17) 1(2839.06,2435.17) 1(2839.16,1508.73) 1(2839.16,1508.73) 1(2839.16,2183.73) 1(2839.16,2183.73) 1(2839.29,1760.06) 1(2839.29,1760.06) 1(2839.29,2435.06) 1(2839.29,2435.06) 1(2839.39,1508.84) 1(2839.39,1508.84) 1(2839.39,2183.84) 1(2839.39,2183.84) 1(2839.53,1759.93) 1(2839.53,1759.93) 1(2839.53,2434.93) 1(2839.53,2434.93) 1(2839.62,1508.98) 1(2839.62,1508.98) 1(2839.62,2183.98) 1(2839.62,2183.98) 1(2839.75,1759.79) 1(2839.75,1759.79) 1(2839.75,2434.79) 1(2839.75,2434.79) 1(2839.85,1509.13) 1(2839.85,1509.13) 1(2839.85,2184.13) 1(2839.85,2184.13) 1(2839.98,1759.63) 1(2839.98,1759.63) 1(2839.98,2434.63) 1(2839.98,2434.63) 1(2840.07,1509.3) 1(2840.07,1509.3) 1(2840.07,2184.3) 1(2840.07,2184.3) 1(2840.2,1759.45) 1(2840.2,1759.45) 1(2840.2,2434.45) 1(2840.2,2434.45) 1(2840.28,1509.49) 1(2840.28,1509.49) 1(2840.28,2184.49) 1(2840.28,2184.49) 1(2840.41,1759.25) 1(2840.41,1759.25) 1(2840.41,2434.25) 1(2840.41,2434.25) 1(2840.49,1509.69) 1(2840.49,1509.69) 1(2840.49,2184.69) 1(2840.49,2184.69) 1(2840.61,1759.04) 1(2840.61,1759.04) 1(2840.61,2434.04) 1(2840.61,2434.04) 1(2840.7,1509.91) 1(2840.7,1509.91) 1(2840.7,2184.91) 1(2840.7,2184.91) 1(2840.81,1758.81) 1(2840.81,1758.81) 1(2840.81,2433.81) 1(2840.81,2433.81) 1(2840.89,1510.15) 1(2840.89,1510.15) 1(2840.89,2185.15) 1(2840.89,2185.15) 1(2841.01,1758.56) 1(2841.01,1758.56) 1(2841.01,2433.56) 1(2841.01,2433.56) 1(2841.08,1510.4) 1(2841.08,1510.4) 1(2841.08,2185.4) 1(2841.08,2185.4) 1(2841.19,1758.3) 1(2841.19,1758.3) 1(2841.19,2433.3) 1(2841.19,2433.3) 1(2841.2,1473.01) 1(2841.2,1473.01) 1(2841.2,1795.84) 1(2841.2,1795.84) 1(2841.2,2148.01) 1(2841.2,2148.01) 1(2841.2,2470.84) 1(2841.2,2470.84) 1(2841.26,1510.67) 1(2841.26,1510.67) 1(2841.26,2185.67) 1(2841.26,2185.67) 1(2841.36,1758.02) 1(2841.36,1758.02) 1(2841.36,2433.02) 1(2841.36,2433.02) 1(2841.43,1510.95) 1(2841.43,1510.95) 1(2841.43,2185.95) 1(2841.43,2185.95) 1(2841.53,1757.73) 1(2841.53,1757.73) 1(2841.53,2432.73) 1(2841.53,2432.73) 1(2841.6,1511.24) 1(2841.6,1511.24) 1(2841.6,2186.24) 1(2841.6,2186.24) 1(2841.69,1757.43) 1(2841.69,1757.43) 1(2841.69,2432.43) 1(2841.69,2432.43) 1(2841.75,1511.55) 1(2841.75,1511.55) 1(2841.75,2186.55) 1(2841.75,2186.55) 1(2841.84,1757.12) 1(2841.84,1757.12) 1(2841.84,2432.12) 1(2841.84,2432.12) 1(2841.89,1511.87) 1(2841.89,1511.87) 1(2841.89,2186.87) 1(2841.89,2186.87) 1(2841.97,1756.79) 1(2841.97,1756.79) 1(2841.97,2431.79) 1(2841.97,2431.79) 1(2842.03,1512.2) 1(2842.03,1512.2) 1(2842.03,2187.2) 1(2842.03,2187.2) 1(2842.1,1756.45) 1(2842.1,1756.45) 1(2842.1,2431.45) 1(2842.1,2431.45) 1(2842.15,1512.54) 1(2842.15,1512.54) 1(2842.15,2187.54) 1(2842.15,2187.54) 1(2842.22,1756.11) 1(2842.22,1756.11) 1(2842.22,2431.11) 1(2842.22,2431.11) 1(2842.26,1512.89) 1(2842.26,1512.89) 1(2842.26,2187.89) 1(2842.26,2187.89) 1(2842.32,1755.75) 1(2842.32,1755.75) 1(2842.32,2430.75) 1(2842.32,2430.75) 1(2842.37,1513.25) 1(2842.37,1513.25) 1(2842.37,2188.25) 1(2842.37,2188.25) 1(2842.42,1755.39) 1(2842.42,1755.39) 1(2842.42,2430.39) 1(2842.42,2430.39) 1(2842.45,1513.62) 1(2842.45,1513.62) 1(2842.45,2188.62) 1(2842.45,2188.62) 1(2842.5,1755.02) 1(2842.5,1755.02) 1(2842.5,2430.02) 1(2842.5,2430.02) 1(2842.53,1513.99) 1(2842.53,1513.99) 1(2842.53,2188.99) 1(2842.53,2188.99) 1(2842.57,1754.64) 1(2842.57,1754.64) 1(2842.57,2429.64) 1(2842.57,2429.64) 1(2842.6,1514.37) 1(2842.6,1514.37) 1(2842.6,2189.37) 1(2842.6,2189.37) 1(2842.63,1754.26) 1(2842.63,1754.26) 1(2842.63,2429.26) 1(2842.63,2429.26) 1(2842.66,1514.75) 1(2842.66,1514.75) 1(2842.66,2189.75) 1(2842.66,2189.75) 1(2842.68,1753.88) 1(2842.68,1753.88) 1(2842.68,2428.88) 1(2842.68,2428.88) 1(2842.7,1515.14) 1(2842.7,1515.14) 1(2842.7,2190.14) 1(2842.7,2190.14) 1(2842.72,1753.49) 1(2842.72,1753.49) 1(2842.72,2428.49) 1(2842.72,2428.49) 1(2842.73,1515.53) 1(2842.73,1515.53) 1(2842.73,2190.53) 1(2842.73,2190.53) 1(2842.74,1753.09) 1(2842.74,1753.09) 1(2842.74,2428.09) 1(2842.74,2428.09) 1(2842.75,1515.92) 1(2842.75,1515.92) 1(2842.75,2190.92) 1(2842.75,2190.92) 1(2842.75,1516.32) 1(2842.75,1516.32) 1(2842.75,1752.54) 1(2842.75,1752.54) 1(2842.75,2191.32) 1(2842.75,2191.32) 1(2842.75,2427.54) 1(2842.75,2427.54) 1(2845.79,1491.71) 1(2845.79,1777.14) 1(2845.79,2166.71) 1(2845.79,2452.14) 1(2845.79,1491.71) 1(2845.79,1777.14) 1(2845.79,2166.71) 1(2845.79,2452.14) 1(2847.07,1508.44) 1(2847.07,1508.44) 1(2847.07,1760.41) 1(2847.07,1760.41) 1(2847.07,2183.44) 1(2847.07,2183.44) 1(2847.07,2435.41) 1(2847.07,2435.41) 1(2847.32,1760.4) 1(2847.32,1760.4) 1(2847.32,2435.4) 1(2847.32,2435.4) 1(2847.42,1508.46) 1(2847.42,1508.46) 1(2847.42,2183.46) 1(2847.42,2183.46) 1(2847.56,1760.37) 1(2847.56,1760.37) 1(2847.56,2435.37) 1(2847.56,2435.37) 1(2847.66,1508.5) 1(2847.66,1508.5) 1(2847.66,2183.5) 1(2847.66,2183.5) 1(2847.81,1760.32) 1(2847.81,1760.32) 1(2847.81,2435.32) 1(2847.81,2435.32) 1(2847.91,1508.56) 1(2847.91,1508.56) 1(2847.91,2183.56) 1(2847.91,2183.56) 1(2848.05,1760.25) 1(2848.05,1760.25) 1(2848.05,2435.25) 1(2848.05,2435.25) 1(2848.15,1508.63) 1(2848.15,1508.63) 1(2848.15,2183.63) 1(2848.15,2183.63) 1(2848.29,1760.17) 1(2848.29,1760.17) 1(2848.29,2435.17) 1(2848.29,2435.17) 1(2848.39,1508.73) 1(2848.39,1508.73) 1(2848.39,2183.73) 1(2848.39,2183.73) 1(2848.52,1760.06) 1(2848.52,1760.06) 1(2848.52,2435.06) 1(2848.52,2435.06) 1(2848.62,1508.84) 1(2848.62,1508.84) 1(2848.62,2183.84) 1(2848.62,2183.84) 1(2848.76,1759.93) 1(2848.76,1759.93) 1(2848.76,2434.93) 1(2848.76,2434.93) 1(2848.78,1485.01) 1(2848.78,1485.01) 1(2848.78,1783.84) 1(2848.78,1783.84) 1(2848.78,2160.01) 1(2848.78,2160.01) 1(2848.78,2458.84) 1(2848.78,2458.84) 1(2848.85,1508.98) 1(2848.85,1508.98) 1(2848.85,2183.98) 1(2848.85,2183.98) 1(2848.99,1759.79) 1(2848.99,1759.79) 1(2848.99,2434.79) 1(2848.99,2434.79) 1(2849.08,1509.13) 1(2849.08,1509.13) 1(2849.08,2184.13) 1(2849.08,2184.13) 1(2849.21,1759.63) 1(2849.21,1759.63) 1(2849.21,2434.63) 1(2849.21,2434.63) 1(2849.3,1509.3) 1(2849.3,1509.3) 1(2849.3,2184.3) 1(2849.3,2184.3) 1(2849.43,1759.45) 1(2849.43,1759.45) 1(2849.43,2434.45) 1(2849.43,2434.45) 1(2849.52,1509.49) 1(2849.52,1509.49) 1(2849.52,2184.49) 1(2849.52,2184.49) 1(2849.64,1759.25) 1(2849.64,1759.25) 1(2849.64,2434.25) 1(2849.64,2434.25) 1(2849.73,1509.69) 1(2849.73,1509.69) 1(2849.73,2184.69) 1(2849.73,2184.69) 1(2849.85,1759.04) 1(2849.85,1759.04) 1(2849.85,2434.04) 1(2849.85,2434.04) 1(2849.93,1509.91) 1(2849.93,1509.91) 1(2849.93,2184.91) 1(2849.93,2184.91) 1(2850.05,1758.81) 1(2850.05,1758.81) 1(2850.05,2433.81) 1(2850.05,2433.81) 1(2850.13,1510.15) 1(2850.13,1510.15) 1(2850.13,2185.15) 1(2850.13,2185.15) 1(2850.24,1758.56) 1(2850.24,1758.56) 1(2850.24,2433.56) 1(2850.24,2433.56) 1(2850.31,1510.4) 1(2850.31,1510.4) 1(2850.31,2185.4) 1(2850.31,2185.4) 1(2850.42,1758.3) 1(2850.42,1758.3) 1(2850.42,2433.3) 1(2850.42,2433.3) 1(2850.49,1510.67) 1(2850.49,1510.67) 1(2850.49,2185.67) 1(2850.49,2185.67) 1(2850.6,1758.02) 1(2850.6,1758.02) 1(2850.6,2433.02) 1(2850.6,2433.02) 1(2850.67,1510.95) 1(2850.67,1510.95) 1(2850.67,2185.95) 1(2850.67,2185.95) 1(2850.76,1757.73) 1(2850.76,1757.73) 1(2850.76,2432.73) 1(2850.76,2432.73) 1(2850.83,1511.24) 1(2850.83,1511.24) 1(2850.83,2186.24) 1(2850.83,2186.24) 1(2850.92,1757.43) 1(2850.92,1757.43) 1(2850.92,2432.43) 1(2850.92,2432.43) 1(2850.98,1511.55) 1(2850.98,1511.55) 1(2850.98,2186.55) 1(2850.98,2186.55) 1(2851.07,1757.12) 1(2851.07,1757.12) 1(2851.07,2432.12) 1(2851.07,2432.12) 1(2851.13,1511.87) 1(2851.13,1511.87) 1(2851.13,2186.87) 1(2851.13,2186.87) 1(2851.21,1756.79) 1(2851.21,1756.79) 1(2851.21,2431.79) 1(2851.21,2431.79) 1(2851.26,1512.2) 1(2851.26,1512.2) 1(2851.26,2187.2) 1(2851.26,2187.2) 1(2851.33,1756.45) 1(2851.33,1756.45) 1(2851.33,2431.45) 1(2851.33,2431.45) 1(2851.38,1512.54) 1(2851.38,1512.54) 1(2851.38,2187.54) 1(2851.38,2187.54) 1(2851.45,1756.11) 1(2851.45,1756.11) 1(2851.45,2431.11) 1(2851.45,2431.11) 1(2851.49,1512.89) 1(2851.49,1512.89) 1(2851.49,2187.89) 1(2851.49,2187.89) 1(2851.56,1755.75) 1(2851.56,1755.75) 1(2851.56,2430.75) 1(2851.56,2430.75) 1(2851.6,1513.25) 1(2851.6,1513.25) 1(2851.6,2188.25) 1(2851.6,2188.25) 1(2851.65,1755.39) 1(2851.65,1755.39) 1(2851.65,2430.39) 1(2851.65,2430.39) 1(2851.69,1513.62) 1(2851.69,1513.62) 1(2851.69,2188.62) 1(2851.69,2188.62) 1(2851.73,1755.02) 1(2851.73,1755.02) 1(2851.73,2430.02) 1(2851.73,2430.02) 1(2851.76,1513.99) 1(2851.76,1513.99) 1(2851.76,2188.99) 1(2851.76,2188.99) 1(2851.81,1754.64) 1(2851.81,1754.64) 1(2851.81,2429.64) 1(2851.81,2429.64) 1(2851.83,1514.37) 1(2851.83,1514.37) 1(2851.83,2189.37) 1(2851.83,2189.37) 1(2851.87,1754.26) 1(2851.87,1754.26) 1(2851.87,2429.26) 1(2851.87,2429.26) 1(2851.89,1514.75) 1(2851.89,1514.75) 1(2851.89,2189.75) 1(2851.89,2189.75) 1(2851.91,1753.88) 1(2851.91,1753.88) 1(2851.91,2428.88) 1(2851.91,2428.88) 1(2851.93,1515.14) 1(2851.93,1515.14) 1(2851.93,2190.14) 1(2851.93,2190.14) 1(2851.95,1753.49) 1(2851.95,1753.49) 1(2851.95,2428.49) 1(2851.95,2428.49) 1(2851.96,1515.53) 1(2851.96,1515.53) 1(2851.96,2190.53) 1(2851.96,2190.53) 1(2851.97,1753.09) 1(2851.97,1753.09) 1(2851.97,2428.09) 1(2851.97,2428.09) 1(2851.98,1515.92) 1(2851.98,1515.92) 1(2851.98,2190.92) 1(2851.98,2190.92) 1(2851.98,1477.82) 1(2851.98,1477.82) 1(2851.98,1516.32) 1(2851.98,1516.32) 1(2851.98,1752.54) 1(2851.98,1752.54) 1(2851.98,1791.04) 1(2851.98,1791.04) 1(2851.98,2152.82) 1(2851.98,2152.82) 1(2851.98,2191.32) 1(2851.98,2191.32) 1(2851.98,2427.54) 1(2851.98,2427.54) 1(2851.98,2466.04) 1(2851.98,2466.04)
  round 61.02 on Mech16: 1(864.93,-734.55) 1(864.93,-634.55) 1(931.3,-141.5) 1(931.3,-41.5) 1(1041.93,1074.45) 1(1041.93,1174.45) 1(1921.3,1943.5) 1(1921.3,2043.5) 1(2434.3,1228.5) 1(2434.3,1328.5)
  round 140 on Mech16: 1(879.94,3225.59)
  round 9.84 on Mech16: 1(1169.8,1353.96) 1(1179.64,1353.96) 1(1628.98,1086.85) 1(1637.48,1086.85) 1(1719.64,926.77) 1(1719.64,946.46) 1(1719.64,1005.51) 1(1719.64,966.14) 1(1719.64,985.83) 1(1755.08,926.77) 1(1755.08,946.46) 1(1755.08,1005.51) 1(1755.08,966.14) 1(1755.08,985.83) 1(1777.95,-209.45) 1(1777.95,-189.77) 1(1777.95,-130.71) 1(1777.95,-170.08) 1(1777.95,-150.4) 1(1813.38,-209.45) 1(1813.38,-189.77) 1(1813.38,-130.71) 1(1813.38,-170.08) 1(1813.38,-150.4) 1(1886.97,966.14) 1(1886.97,985.83) 1(1886.97,926.77) 1(1886.97,946.46) 1(1886.97,1005.51) 1(1922.4,966.14) 1(1922.4,985.83) 1(1922.4,926.77) 1(1922.4,946.46) 1(1922.4,1005.51) 1(1945.27,-170.08) 1(1945.27,-150.4) 1(1945.27,-209.45) 1(1945.27,-189.77) 1(1945.27,-130.71) 1(1980.7,-170.08) 1(1980.7,-150.4) 1(1980.71,-209.45) 1(1980.71,-189.77) 1(1980.71,-130.71) 1(2237.92,7.13) 1(2237.92,26.82) 1(2237.92,46.5) 1(2237.92,66.19) 1(2237.92,85.87) 1(2273.35,7.13) 1(2273.35,26.82) 1(2273.35,46.5) 1(2273.35,66.19) 1(2273.35,85.87) 1(2405.24,7.13) 1(2405.24,26.82) 1(2405.24,46.5) 1(2405.24,66.19) 1(2405.24,85.87) 1(2440.67,7.13) 1(2440.67,26.82) 1(2440.67,46.5) 1(2440.67,66.19) 1(2440.67,85.87) 1(2481.13,1620.73) 1(2514.64,2265.65)
  round 19.69 on Mech16: 1(1174.72,1353.96)
  round 27.56 on Mech16: 1(1213.11,1384.28)
  round 23.62 on Mech16: 1(1232.79,1415.77) 1(1256.41,1415.77) 1(1852.52,313.68)
  round 47.24 on Mech16: 1(1244.6,1415.77) 1(2737.13,1496.05) 1(2737.13,1771.64) 1(2737.13,2171.05) 1(2737.13,2446.64) 1(2764.69,1496.05) 1(2764.69,1771.64) 1(2764.69,2171.05) 1(2764.69,2446.64)
  round 125.2 on Mech16: 1(1278.31,-1395.55) 1(1778.31,-1395.55)
  round 8 on Mech16: 1(1433.93,918.16) 1(1433.93,948.5) 1(1589.65,674.7) 1(1589.65,674.7) 1(1597.09,614.84) 1(1597.09,682.15) 1(1597.09,682.15) 1(1598.73,682.15) 1(1606.17,674.7) 1(1606.17,674.7)
  round 6.89 on Mech16: 1(1653.35,1082.03) 1(1653.35,1088.92) 1(1653.35,1107.62) 1(1653.35,1114.51) 1(1653.35,1133.22) 1(1653.35,1140.11) 1(1653.35,1158.81) 1(1653.35,1165.7) 1(1713.39,1082.03) 1(1713.39,1088.92) 1(1713.39,1107.62) 1(1713.39,1114.51) 1(1713.39,1133.22) 1(1713.39,1140.11) 1(1713.39,1158.81) 1(1713.39,1165.7) 1(1877.76,1082.03) 1(1877.76,1088.92) 1(1877.76,1107.62) 1(1877.76,1114.51) 1(1877.76,1133.22) 1(1877.76,1140.11) 1(1877.76,1158.81) 1(1877.76,1165.7) 1(1937.8,1082.03) 1(1937.8,1088.92) 1(1937.8,1107.62) 1(1937.8,1114.51) 1(1937.8,1133.22) 1(1937.8,1140.11) 1(1937.8,1158.81) 1(1937.8,1165.7)
  round 6.69 on Mech16: 1(1719.34,68.1) 1(1719.34,91.72) 1(1725.56,676.1) 1(1725.56,699.72) 1(1813.82,68.1) 1(1813.82,91.72) 1(1820.05,676.1) 1(1820.05,699.72) 1(1825.26,-8.89) 1(1825.26,61.98) 1(1828.44,706.11) 1(1828.44,776.98) 1(1904,-8.89) 1(1904,61.98) 1(1907.18,706.11) 1(1907.18,776.98) 1(1917.26,-6.89) 1(1917.26,63.98) 1(1917.44,705.11) 1(1917.44,775.98) 1(1996,-6.89) 1(1996,63.98) 1(1996.18,705.11) 1(1996.18,775.98) 1(2007.9,676.1) 1(2007.9,699.72) 1(2008.9,68.1) 1(2008.9,91.72) 1(2102.39,676.1) 1(2102.39,699.72) 1(2103.39,68.1) 1(2103.39,91.72)
  round 2.76 on Mech16: 1(1723.27,26.76) 1(1723.27,26.76) 1(1723.27,133.06) 1(1723.27,133.06) 1(1729.5,634.76) 1(1729.5,634.76) 1(1729.5,741.06) 1(1729.5,741.06) 1(1809.89,26.76) 1(1809.89,26.76) 1(1809.89,133.06) 1(1809.89,133.06) 1(1816.11,634.76) 1(1816.11,634.76) 1(1816.11,741.06) 1(1816.11,741.06) 1(1827.22,-42.35) 1(1827.22,-42.35) 1(1827.22,95.44) 1(1827.22,95.44) 1(1830.41,672.65) 1(1830.41,672.65) 1(1830.41,810.44) 1(1830.41,810.44) 1(1902.03,-42.35) 1(1902.03,-42.35) 1(1902.03,95.44) 1(1902.03,95.44) 1(1905.21,672.65) 1(1905.21,672.65) 1(1905.21,810.44) 1(1905.21,810.44) 1(1919.22,-40.35) 1(1919.22,-40.35) 1(1919.22,97.44) 1(1919.22,97.44) 1(1919.41,671.65) 1(1919.41,671.65) 1(1919.41,809.44) 1(1919.41,809.44) 1(1994.03,-40.35) 1(1994.03,-40.35) 1(1994.03,97.44) 1(1994.03,97.44) 1(1994.21,671.65) 1(1994.21,671.65) 1(1994.21,809.44) 1(1994.21,809.44) 1(2011.84,634.76) 1(2011.84,634.76) 1(2011.84,741.06) 1(2011.84,741.06) 1(2012.84,26.76) 1(2012.84,26.76) 1(2012.84,133.06) 1(2012.84,133.06) 1(2098.45,634.76) 1(2098.45,634.76) 1(2098.45,741.06) 1(2098.45,741.06) 1(2099.45,26.76) 1(2099.45,26.76) 1(2099.45,133.06) 1(2099.45,133.06)
  round 21.42 on Mech16: 1(1833.13,1591.75)
  round 3.15 on Mech16: 1(1847.97,1472.27) 1(1847.97,1472.27) 1(1847.97,1574.63) 1(1847.97,1574.63) 1(1861.75,1554.95) 1(1877.49,1554.95) 1(1977.89,1472.27) 1(1977.89,1472.27) 1(1977.89,1574.63) 1(1977.89,1574.63)
  round 18.9 on Mech16: 1(1869.62,1554.95)
  round 74 on Mech16: 1(2259.43,515.38)
  round 26.34 on Mech16: 1(2289.68,930.17)
  round 80 on Mech16: 1(2307.3,-857.5)
  round 69.78 on Mech16: 1(2380.83,-266.02)
  round 22.01 on Mech16: 1(2473.77,1576.45)
  round 1.97 on Mech16: 1(2477.19,1620.73) 1(2485.07,1620.73) 1(2510.71,2265.65) 1(2518.58,2265.65)
  round 29.53 on Mech16: 1(2495.9,-1275.12) 1(2495.9,-1097.95) 1(2525.43,-1275.12) 1(2525.43,-1097.95)
  round 59.06 on Mech16: 1(2569.72,-1001.49) 1(2687.83,-1001.49) 1(2746.89,-1245.59) 1(2746.89,-1127.48)
  round 20.19 on Mech16: 1(2617.4,1685.9) 1(2617.4,2360.9)
  round 33.46 on Mech16: 1(2630.19,-755.08) 1(2630.19,-721.61) 1(2630.19,-310.08) 1(2630.19,-276.61) 1(2663.66,-755.08) 1(2663.66,-721.61) 1(2663.66,-310.08) 1(2663.66,-276.61)
  round 66.93 on Mech16: 1(2646.93,-600.55) 1(2646.93,-462.76) 1(2646.93,-155.55) 1(2646.93,-17.76)
  round 30.12 on Mech16: 1(2693.87,680.39) 1(2693.87,710.51) 1(2723.99,680.39) 1(2723.99,710.51)
  round 157.48 hole 118.11: TH1(91.81,3572.29) TH2(91.81,124.38) TH2(91.81,1332.29) TH2(1711.42,124.38) TH2(3065.87,1332.29) TH9(3065.87,3572.29)
  round 160 hole 160 unplated: ""(150,-204.34) ""(150,3905.13) ""(3018.31,-204.34) ""(3018.31,3905.13)

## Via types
v1: diameter 13.77, hole 7, Top Layer to L2_GND1, tented both sides, 3444 vias
v2: diameter 18, hole 8, Top Layer to Bottom Layer, tented both sides, 911 vias
v3: diameter 13.77, hole 7, Top Layer to L2_GND1, tented top, 9 vias
v4: diameter 19.68, hole 7.87, Top Layer to Bottom Layer, 4 vias
v5: diameter 19.68, hole 7.87, Top Layer to Bottom Layer, tented both sides, 2 vias

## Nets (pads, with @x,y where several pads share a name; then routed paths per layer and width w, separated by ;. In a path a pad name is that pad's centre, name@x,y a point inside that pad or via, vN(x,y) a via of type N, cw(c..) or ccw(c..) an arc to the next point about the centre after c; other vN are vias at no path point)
3V3_LDO_EN: R11.2 R241.2 U13.4 | length 84.5
  Top Layer w10.8: U13.4@2295.17,430.15 R241.2@2325.17,430.15 R11.2@2379.68,430.15
5V_IN_USB: C42.2 C46.2 C47.1 C55.1 C66.1 C67.2 C84.1 C85.2 D1.1 D12.1 R1.2 R27.1 R35.2 R36.2 TP14.1 U13.6 U14.2 | length 737.1
  Top Layer w20: R27.1@2116.91,651.13 2116.91,615.09 2163.62,568.39 2276.37,568.39 ; C42.2@2293.85,518.22 2298.92,523.29 2298.92,545.84 2276.37,568.39 ; 2310.4,580.15 2298.63,568.39 2276.37,568.39 ; v2(2319.69,920.91) 2335.18,936.4 2367.6,936.4 2391.36,912.64 R36.2@2391.36,881.48 2391.36,818.3 2382.35,809.29 ; D1.1@2745.09,411.17 2828.68,411.17 2853.44,386.41 R1.2@2853.44,336.42
  Bottom Layer w15: R35.2@2263.21,924.94 2314.85,924.94 2318.88,920.91 v2(2319.69,920.91)
  other v2: 2717.75,456.69 2750.24,457.22 2786.42,456.69 2703.76,478.88 2733.6,478.88 2766.87,478.88 2708.37,1287.47 2730.56,1301.46 2708.37,1317.31 2730.03,1333.95 2708.37,1350.58 2730.56,1369.48
5V_OVP2: R35.1 R74.2 U14.4 | length 129
  Top Layer w7: U14.4@2233.17,810.34 2233.17,829.23 2240.13,836.19 v2(2240.13,838.53)
  Top Layer w10.8: v2(2240.13,838.53) 2251.98,850.37 2253.34,850.37 2263.39,860.43 R74.2@2263.39,877.3
  Bottom Layer w8.7: v2(2240.13,838.53) 2250.71,849.1 2250.71,861.26 2263.21,873.76 R35.1@2263.21,877.7
12V_DC_JACK: C48.1 C63.1 D2.2 J7.1 U10.4 U10.5 U10.6
12V_OVP1: R4.1 R20.2 U14.5 | length 107.9
  Top Layer w7: U14.5@2213.49,810.34 v2@2213.49,836.46
  Top Layer w10.8: v2(2213.32,836.62) 2213.49,836.46 2213.49,877.06 R4.1@2213.72,877.3
  Bottom Layer w8.7: v2(2213.32,836.62) 2213.57,836.87 R20.2@2213.57,877.18
CAN1_STB: R131.2 R133.2 R144.2 U19.8 | length 130
  Top Layer w10.8: U19.8@354.01,1570.14 R144.2@354.01,1510.14 R131.2@384.01,1510.14 R133.2@384.01,1470.14
CAN_FD_B_H: J8.3 R130.2 U19.7 | length 283.1
  Top Layer w4.3: J8.3@158.07,1539.71 163.08,1544.71 163.08,1583.65 215.71,1636.29 260.31,1636.29 266.32,1630.27 266.32,1629.8 273.54,1622.58 274.01,1622.58 R130.2@274.01,1620.14 ; R130.2@274.01,1622.93 274.83,1622.93 281.71,1629.8 281.71,1630.62 291.33,1640.24 305.21,1640.24 325.31,1620.14 U19.7@354.01,1620.14
CAN_FD_B_L: J8.1 R140.1 U19.6 | length 281.8
  Top Layer w4.3: J8.1@158.07,1739.71 158.07,1705.6 217.58,1646.09 252.12,1646.09 266.32,1660.29 266.32,1660.48 R140.1@274.01,1668.17 ; R140.1@274.01,1670.14 R140.1@274.01,1668.17 ; U19.6@354.01,1670.14 324.77,1670.14 304.67,1650.04 292.15,1650.04 281.71,1660.48 R140.1@274.01,1668.17
CAN_FD_B_PHY_RX: R143.1 U1.U12 | length 1868.5
  Top Layer w4: v2(1701.04,2370.75) 1704.25,2370.75 1714.88,2381.38 1725.16,2381.38 U1.U12@1750.59,2381.36
  Top Layer w10.8: R143.1@661.15,1720.39 v2(661.15,1745.51)
  L3_SIG1 w6: v2(597.33,2339.51) 597.33,2309.26 611.54,2295.05 611.54,1987.82 596.55,1972.82 596.55,1810.11 v2(661.15,1745.51)
  L6_SIG2 w6: v2(597.33,2339.51) 621.8,2363.98 664.79,2363.98 688.43,2387.62 1029.3,2387.62 1077.45,2339.47 1201.86,2339.47 1216,2353.61 1528.36,2353.61 1683.9,2353.61 v2(1701.04,2370.75)
CAN_FD_B_PHY_TX: R132.1 U1.R11 | length 2101
  Top Layer w4: U1.R11@1789.96,2401.27 1789.96,2394.98 1795.23,2389.72 v2(1795.23,2386.2)
  Top Layer w10.8: v2(526.37,1543.25) 526.99,1542.64 R132.1@526.99,1517.78
  L3_SIG1 w6: v2(526.37,1543.25) 567.88,1584.76 567.88,2153.62 v2(583.47,2169.21)
  L6_SIG2 w6: v2(583.47,2169.21) 604.43,2190.17 1055.55,2190.17 1113.03,2247.65 1140,2247.65 1225.03,2332.68 1528.36,2332.68 1577.53,2332.68 1586.93,2342.08 1738.63,2342.08 1777.78,2302.93 1797.61,2302.93 1824.45,2329.77 1824.45,2344.16 1810.98,2357.62 1810.98,2370.44 v2(1795.23,2386.2)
